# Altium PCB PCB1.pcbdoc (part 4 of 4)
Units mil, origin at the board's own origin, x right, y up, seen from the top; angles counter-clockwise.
Board outline 4701.34 x 4268.46 mil, 2 copper layers (Top Layer, Bottom Layer); 341 components, 58 nets, 1384 pads, 312 vias.
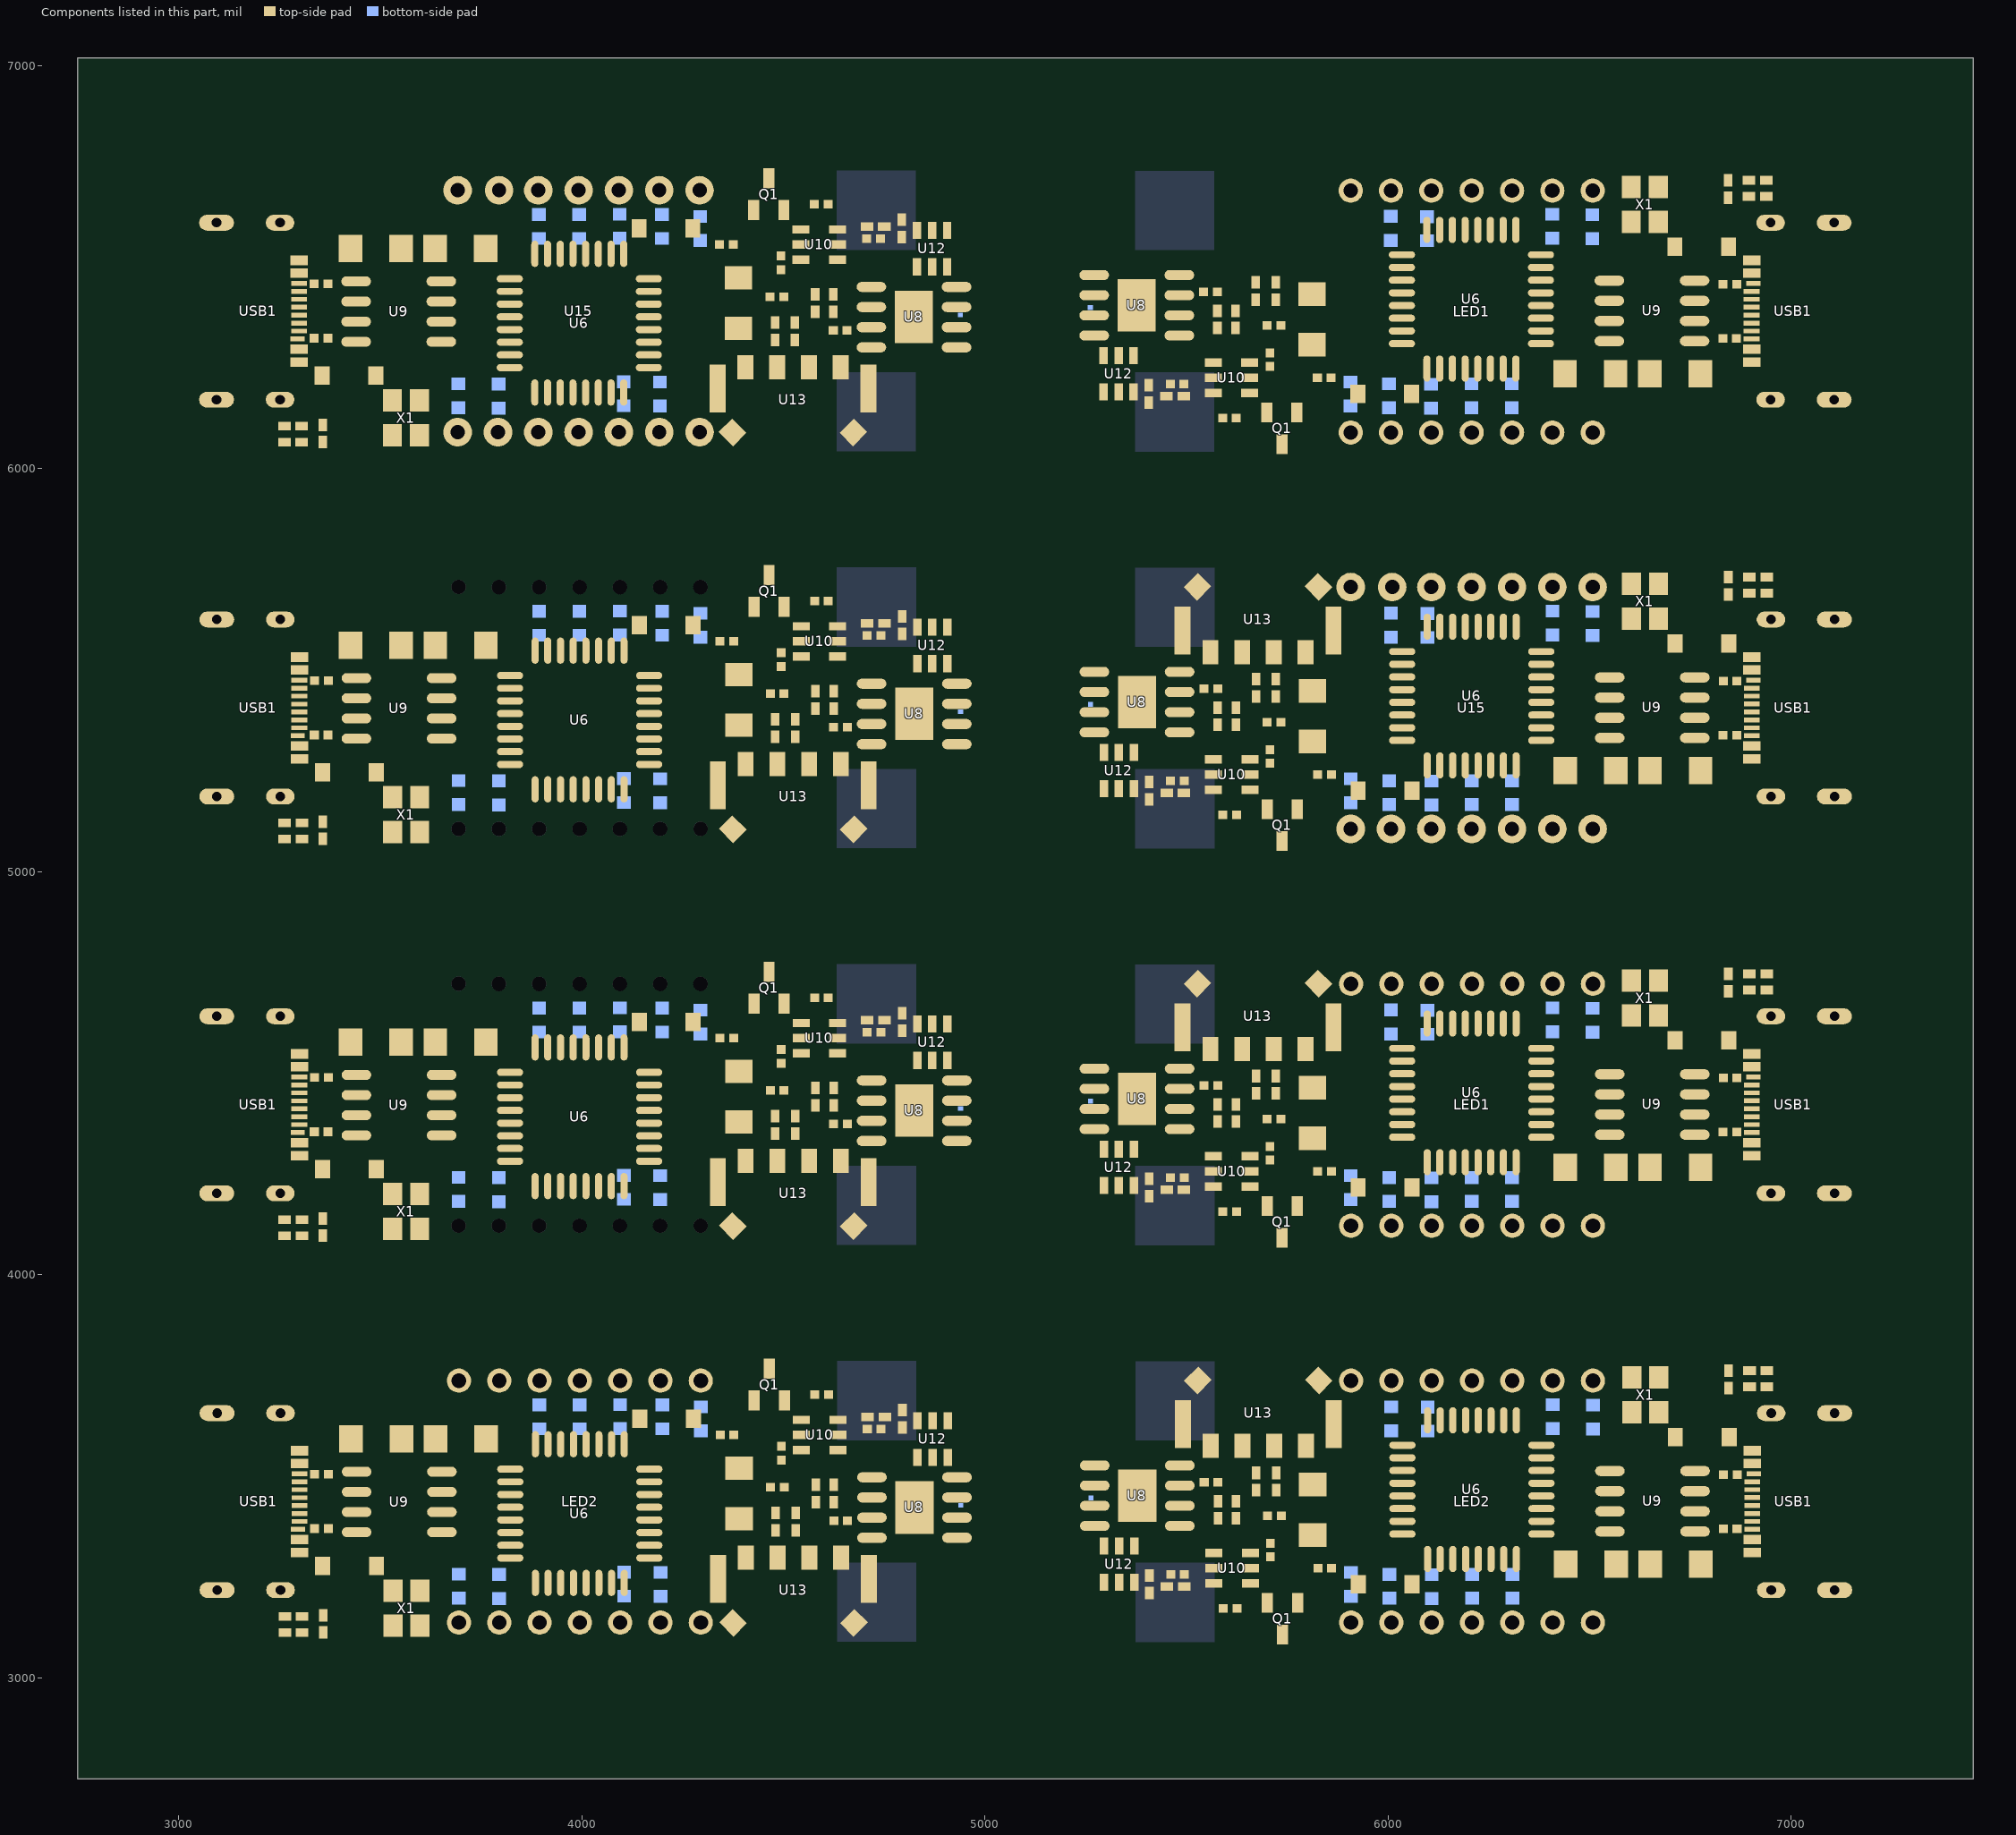
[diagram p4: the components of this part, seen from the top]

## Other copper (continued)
Multi-Layer:
  region net $1N14266: 3724.78,5706.34 cw(c3694.78,5706.34) 3664.78,5706.34 cw(c3694.78,5706.34)
  region net $1N14266: 3824.68,5706.08 cw(c3794.68,5706.08) 3764.68,5706.08 cw(c3794.68,5706.08)
  region net $1N14266: 3924.68,5706.08 cw(c3894.68,5706.08) 3864.68,5706.08 cw(c3894.68,5706.08)
  region net $1N14266: 4024.68,5706.08 cw(c3994.68,5706.08) 3964.68,5706.08 cw(c3994.68,5706.08)
  region net $1N14266: 4124.68,5706.08 cw(c4094.68,5706.08) 4064.68,5706.08 cw(c4094.68,5706.08)
  region net $1N14266: 3724.68,5106.08 cw(c3694.68,5106.08) 3664.68,5106.08 cw(c3694.68,5106.08)
  region net $1N14266: 3824.68,5106.08 cw(c3794.68,5106.08) 3764.68,5106.08 cw(c3794.68,5106.08)
  region net $1N14266: 3924.68,5106.08 cw(c3894.68,5106.08) 3864.68,5106.08 cw(c3894.68,5106.08)
  region net $1N14266: 4024.68,5106.08 cw(c3994.68,5106.08) 3964.68,5106.08 cw(c3994.68,5106.08)
  region net $1N14266: 4124.68,5106.08 cw(c4094.68,5106.08) 4064.68,5106.08 cw(c4094.68,5106.08)
  region net $1N14266: 4224.78,5106.34 cw(c4194.78,5106.34) 4164.78,5106.34 cw(c4194.78,5106.34)
  region net $1N14266: 4324.78,5106.34 cw(c4294.78,5106.34) 4264.78,5106.34 cw(c4294.78,5106.34)
  region net $1N14266: 4224.68,5706.08 cw(c4194.68,5706.08) 4164.68,5706.08 cw(c4194.68,5706.08)
  region net $1N14266: 4324.68,5706.08 cw(c4294.68,5706.08) 4264.68,5706.08 cw(c4294.68,5706.08)
  region net $1N14266: 3724.78,4722.09 cw(c3694.78,4722.09) 3664.78,4722.09 cw(c3694.78,4722.09)
  region net $1N14266: 3824.68,4721.83 cw(c3794.68,4721.83) 3764.68,4721.83 cw(c3794.68,4721.83)
  region net $1N14266: 3924.68,4721.83 cw(c3894.68,4721.83) 3864.68,4721.83 cw(c3894.68,4721.83)
  region net $1N14266: 4024.68,4721.83 cw(c3994.68,4721.83) 3964.68,4721.83 cw(c3994.68,4721.83)
  region net $1N14266: 4124.68,4721.83 cw(c4094.68,4721.83) 4064.68,4721.83 cw(c4094.68,4721.83)
  region net $1N14266: 4224.68,4721.83 cw(c4194.68,4721.83) 4164.68,4721.83 cw(c4194.68,4721.83)
  region net $1N14266: 4324.68,4721.83 cw(c4294.68,4721.83) 4264.68,4721.83 cw(c4294.68,4721.83)
  region net $1N14266: 3724.68,4121.83 cw(c3694.68,4121.83) 3664.68,4121.83 cw(c3694.68,4121.83)
  region net $1N14266: 3824.68,4121.83 cw(c3794.68,4121.83) 3764.68,4121.83 cw(c3794.68,4121.83)
  region net $1N14266: 3924.68,4121.83 cw(c3894.68,4121.83) 3864.68,4121.83 cw(c3894.68,4121.83)
  region net $1N14266: 4024.68,4121.83 cw(c3994.68,4121.83) 3964.68,4121.83 cw(c3994.68,4121.83)
  region net $1N14266: 4124.68,4121.83 cw(c4094.68,4121.83) 4064.68,4121.83 cw(c4094.68,4121.83)
  region net $1N14266: 4224.78,4122.09 cw(c4194.78,4122.09) 4164.78,4122.09 cw(c4194.78,4122.09)
  region net $1N14266: 4324.78,4122.09 cw(c4294.78,4122.09) 4264.78,4122.09 cw(c4294.78,4122.09)

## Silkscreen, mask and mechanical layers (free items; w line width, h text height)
Mechanical Layer:
  drawing of 250 lines, arcs and shapes, not listed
